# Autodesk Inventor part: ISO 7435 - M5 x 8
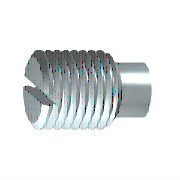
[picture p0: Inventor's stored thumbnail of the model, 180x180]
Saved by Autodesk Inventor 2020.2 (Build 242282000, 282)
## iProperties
Manager: www.cadconsulting.pl
Company: Fabian Stasiak CAD Consulting
Created: 2014-02
Part Number: ISO 7435 - M5 x 8
Material: Stal nierdzewna 440C
Description: Wkręty dociskowe z rowkiem z długim czopkiem
Document SubType Name: Modeling
Standard: ISO 7435
Designer: F.Stasiak
Standard Revision: First edition 1983-09-01
Standards Organization: ISO
Language: pl-PL
Size Designation: M5 x 8
Categories: <MemberInstance><Categories><Category DisplayName="Mocowania" InternalName="e4da775c-781d-43d5-af7c-5136215cf5a6" Mnemonic="FSTN"><Category DisplayName="Śruby"
Density: 7.75 g/cm^3
Appearance: Częściowo polerowana
IsCustomPart: 0
Author: F.Stasiak
Subject: Zbiór ćwiczeń. Autodesk Inventor 2020. Kurs podstawowy
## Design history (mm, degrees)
sketch "Szkic1"
  geometry: L1 (0, 0)-(8, 0); L2 (8, 0)-(8, 2.5); L3 (8, 2.5)-(2.75, 2.5); L4 (0, -0.5)-(0, 3) reference; L5 (0, 1.75)-(0, 0); L6 (0, 1.75)-(2.75, 1.75); L7 (2.75, 1.75)-(2.75, 2.5)
  constraints: 13 end point, 4 perpendicular, 2 parallel, 1 collinear, 1 point on line
  dimensions: "d1" = 8 distance from line of L2 L5.start (= NLG); "d2" = 3.5 diameter of L5.start L1 (= SPD); "d13" = 5 diameter of L3 L1 (= NND); "d14" = 2.75 distance of L5.start L6.end (= ZLG)
revolve "Bryła" sketch "Szkic1" stored, may be unused: angle "d6" = 90 deg
sketch "Szkic2"
  geometry: L1 (8, 2.009)-(8, -2.009) reference; L2 (6.464, 0)-(8.256, 0) reference; L3 (8, 0.4)-(6.72, 0.4); L4 (6.72, 0.4)-(6.72, 0); L5 (6.72, -0.4)-(6.72, 0); L6 (6.72, -0.4)-(8, -0.4)
  constraints: 8 end point, 3 point on line, 2 perpendicular, 1 parallel, 1 symmetric about line, 1 other
  dimensions: "d8" = 0.4 distance between parallel lines of L2 L3 (= 0.5 x SBR); "d9" = 1.28 distance between parallel lines of L1 L4 (= STI)
extrude "Szczelina" cut sketch "Szkic2" stored distance "d10" = 5 (= NND); taper "d11" = 0 deg
workaxis "Work Axis1"
workplane "Work Plane1"
body "Solid1"
chamfer "Faza1" distance "d3" = 0.49076 (= -0.5 x GD1 + 0.5 x NND); stored, may be unused: angle "d4" = 60 deg (= FAWI), second distance "d37" = 0.49076 (= -0.5 x GD1 + 0.5 x NND)
feature "Gwint" dims "d5" = 5.25 (= NLG - ZLG), "d7" = 0
chamfer "Faza2" distance "d15" = 0.75 (= -0.5 x SPD + 0.5 x NND); stored, may be unused: angle "d16" = 60 deg (= FAWI), second distance "d38" = 0.75 (= -0.5 x SPD + 0.5 x NND)
other parameters: "NND" = 5 [user parameter; used in 6 equation terms], "NLG" = 8 [user parameter; used in 2 equation terms], "FAWI" = 60 deg [user parameter; used in 2 equation terms], "GD1" = 4.01848 (= THREADDIA - 1.2269 x PTC) [user parameter; used in 2 equation terms], "d0" = 0, "FAWI1" = 45 deg [user parameter], "SPD" = 3.5 [user parameter; used in 3 equation terms], "SBR" = 0.8 [user parameter; used in 1 equation term], "STI" = 1.28 [user parameter; used in 1 equation term], "ZLG" = 2.75 [user parameter; used in 2 equation terms], "d17" = 0, "d39" = 90 deg, "d40" = 0, "GUL" = 0.49076 (= 0.61345 x PTC) [user parameter], "TPU" = 12.5 (computed from PTC) [user parameter], "THREADDIA" = 5 [user parameter; used in 1 equation term], "TOA" = 30 deg [user parameter], "PTC" = 0.8 [user parameter; used in 4 equation terms], "GAL" = 0.49076 (= 0.61345 x PTC) [user parameter]
